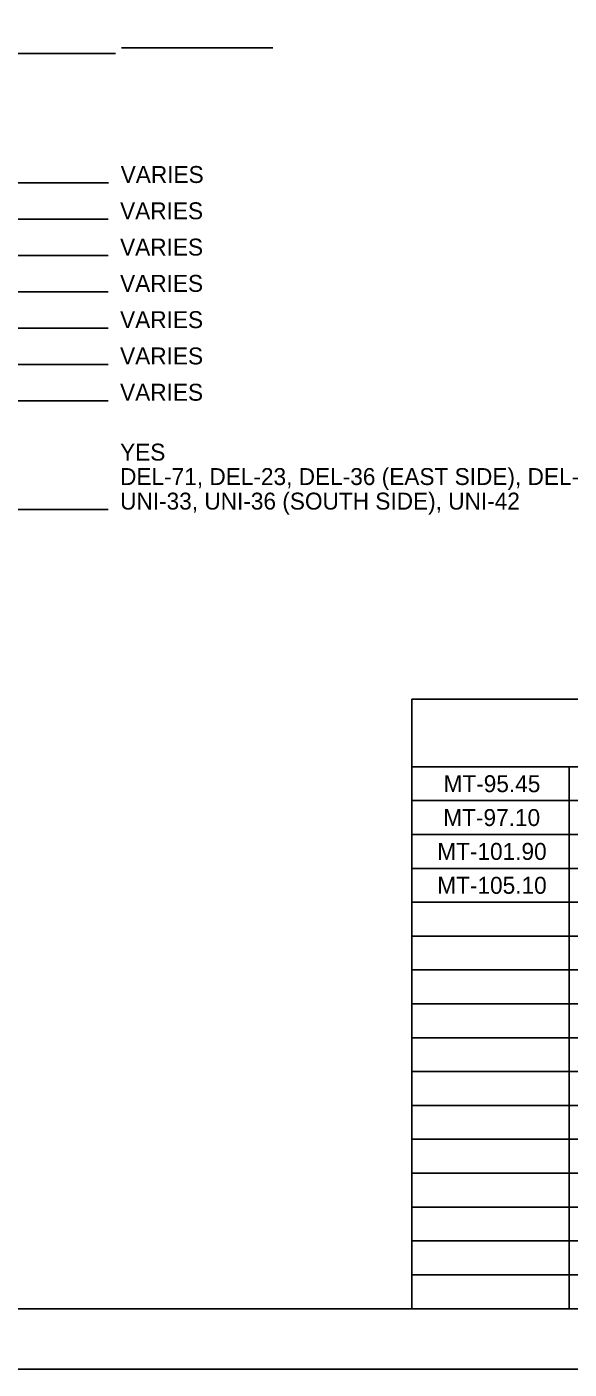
# Model space of a CAD drawing. Extents: x 0 to 34, y 0 to 22.
# Drawn here: x 6.97 to 11.45, y 0 to 11.1 of the extents above; entities that cross this region are included whole.
import ezdxf

# ---------------------------------------------------------------- set-up
doc = ezdxf.new("R2010")
doc.units = 0
for name, color, linetype in [('SH_Border', 7, 'Continuous'), ('SH_Cut_Line', 7, 'Continuous'), ('SH_Data', 7, 'Continuous'), ('SH_Text', 7, 'Continuous')]:
    doc.layers.add(name, color=color, linetype=linetype)

msp = doc.modelspace()

# ---------------------------------------------------------------- linework, layer by layer
at = {"layer": 'SH_Border'}
msp.add_lwpolyline([(1.5, 21.5), (33.5, 21.5), (33.5, 0.5), (1.5, 0.5)], close=True, dxfattribs=at)
at = {"layer": 'SH_Cut_Line'}
msp.add_lwpolyline([(0, 0), (34, 0), (34, 22), (0, 22)], close=True, dxfattribs=at)
at = {"layer": 'SH_Data'}
for p, q in [((7.7, 10.877), (3.347, 10.877)), ((9, 10.922), (7.75, 10.922)), ((7.642, 9.806), (3.871, 9.806)), ((7.637, 9.506), (4.189, 9.506)), ((7.637, 9.206), (4.872, 9.206)), ((7.637, 8.906), (4.604, 8.906)), ((7.637, 8.606), (4.189, 8.606)), ((7.637, 8.306), (3.346, 8.306)), ((7.637, 8.006), (3.242, 8.006)), ((7.637, 7.106), (3.267, 7.106)), ((10.15, 5.54), (23.162, 5.54)), ((10.15, 5.54), (10.15, 0.5)), ((10.15, 4.98), (23.162, 4.98)), ((11.451, 4.98), (11.451, 0.5)), ((10.15, 4.7), (23.162, 4.7)), ((10.15, 4.42), (23.162, 4.42)), ((10.15, 4.14), (23.162, 4.14)), ((10.15, 3.86), (23.162, 3.86)), ((10.15, 3.58), (23.162, 3.58)), ((10.15, 3.3), (23.162, 3.3)), ((10.15, 3.02), (23.162, 3.02)), ((10.15, 2.74), (23.162, 2.74)), ((10.15, 2.46), (23.162, 2.46)), ((10.15, 2.18), (23.162, 2.18)), ((10.15, 1.9), (23.162, 1.9)), ((10.15, 1.62), (23.162, 1.62)), ((10.15, 1.34), (23.162, 1.34)), ((10.15, 1.06), (23.162, 1.06)), ((10.15, 0.78), (23.162, 0.78)), ((10.15, 0.5), (23.162, 0.5))]:
    msp.add_line(p, q, dxfattribs=at)

# ---------------------------------------------------------------- texts
at = {"layer": 'SH_Text'}
for s, p in [('VARIES', (7.742, 9.806)), ('VARIES', (7.737, 9.506)), ('VARIES', (7.737, 9.206)), ('VARIES', (7.737, 8.906)), ('VARIES', (7.737, 8.606)), ('VARIES', (7.737, 8.306)), ('VARIES', (7.737, 8.006)), ('YES ', (7.737, 7.511)), ('DEL-71, DEL-23, DEL-36 (EAST SIDE), DEL-42 (SOUTH SIDE)', (7.737, 7.309)), ('UNI-33, UNI-36 (SOUTH SIDE), UNI-42', (7.737, 7.106)), ('MT-95.45', (10.413, 4.77)), ('MT-97.10', (10.411, 4.49)), ('MT-101.90', (10.361, 4.21)), ('MT-105.10', (10.361, 3.93))]:
    msp.add_text(s, height=0.14, dxfattribs=at).set_placement(p)

doc.saveas('drawing.dxf')
